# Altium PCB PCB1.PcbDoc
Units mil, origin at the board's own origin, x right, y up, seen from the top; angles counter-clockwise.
Board outline 2353 x 1336 mil, 2 copper layers (Top Layer, Bottom Layer), stack 60.4 mil thick; 21 components, 12 nets, 70 pads, 21 vias.
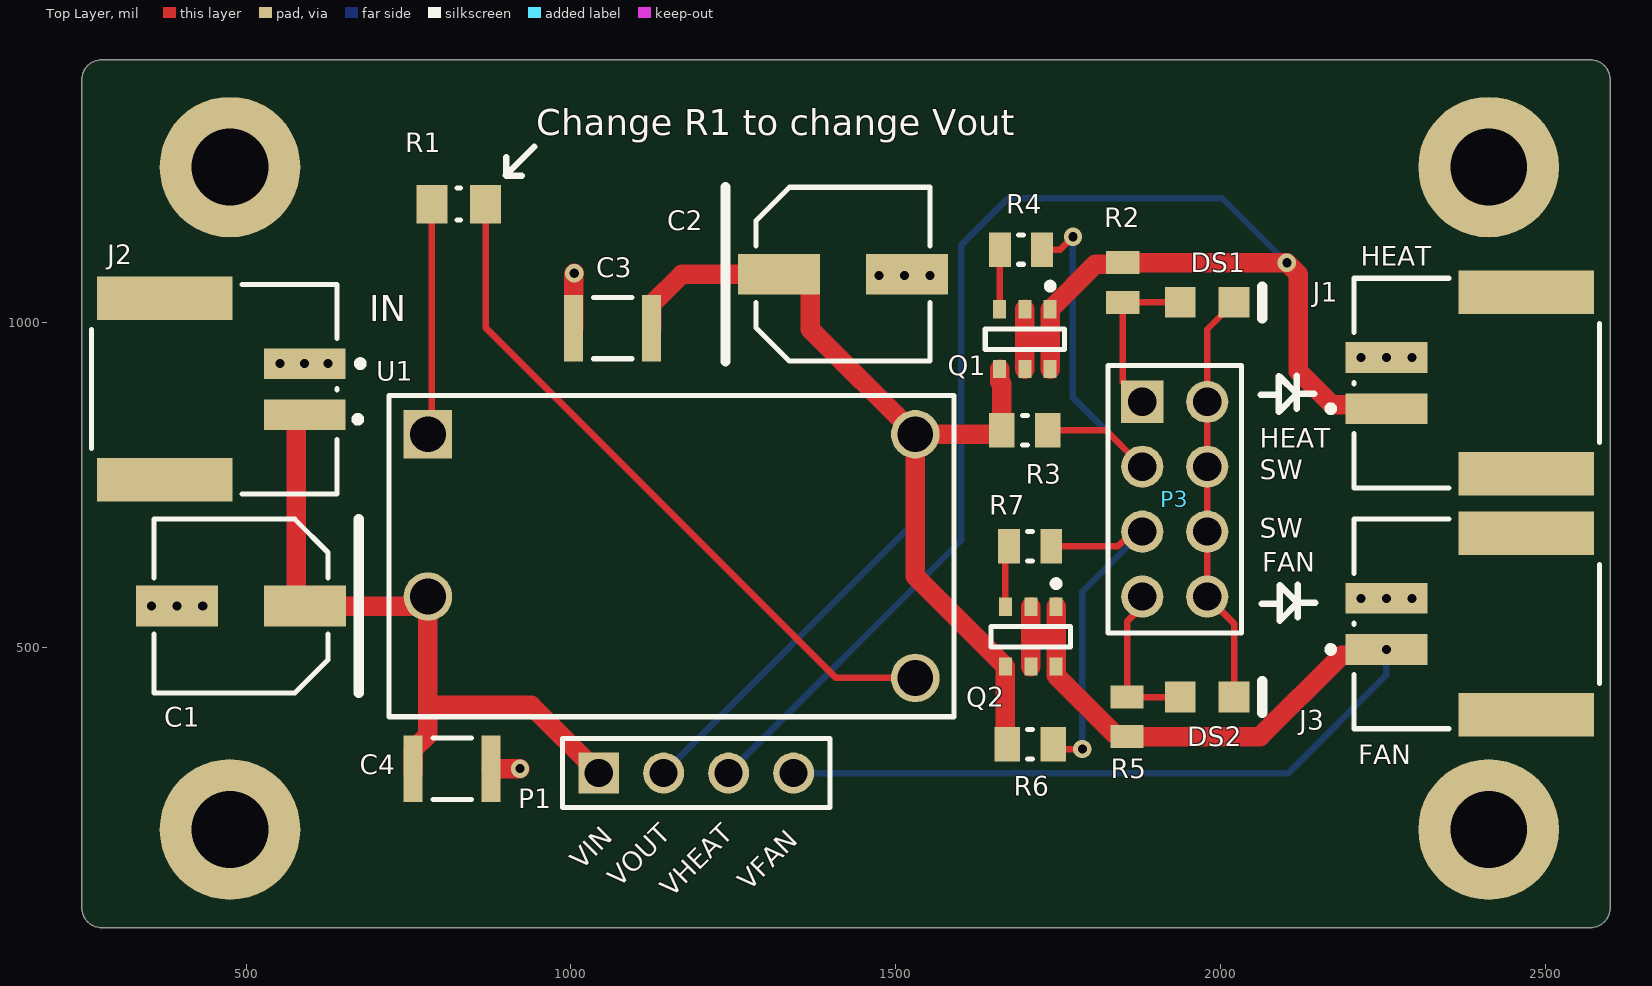
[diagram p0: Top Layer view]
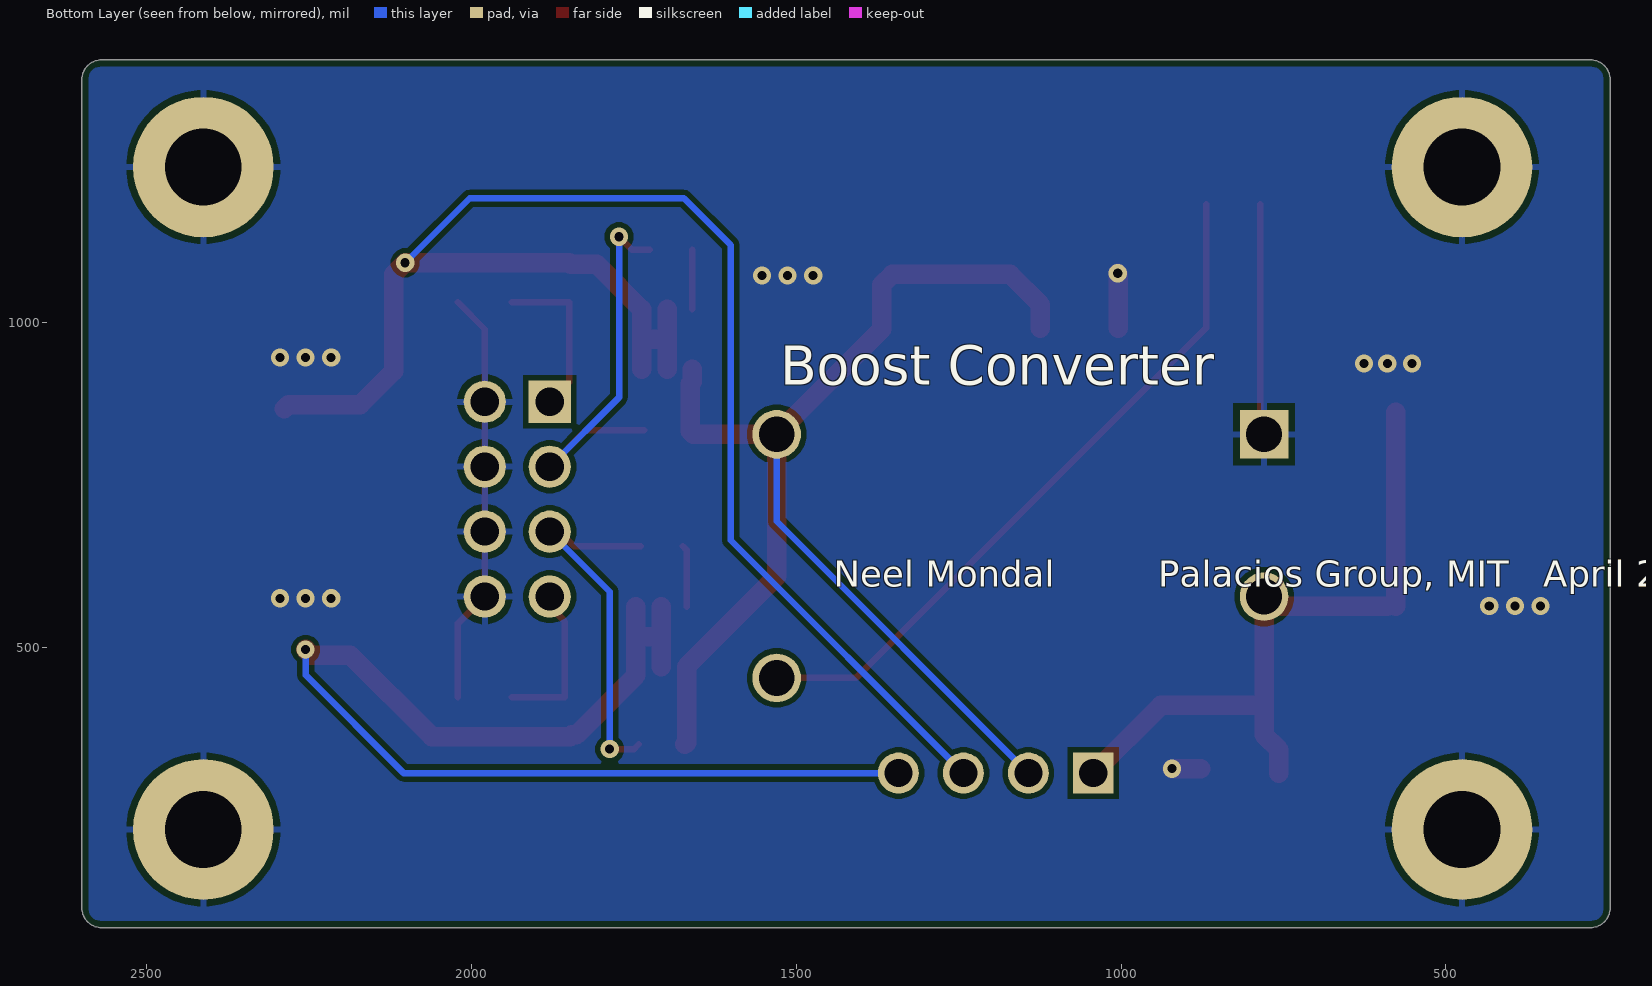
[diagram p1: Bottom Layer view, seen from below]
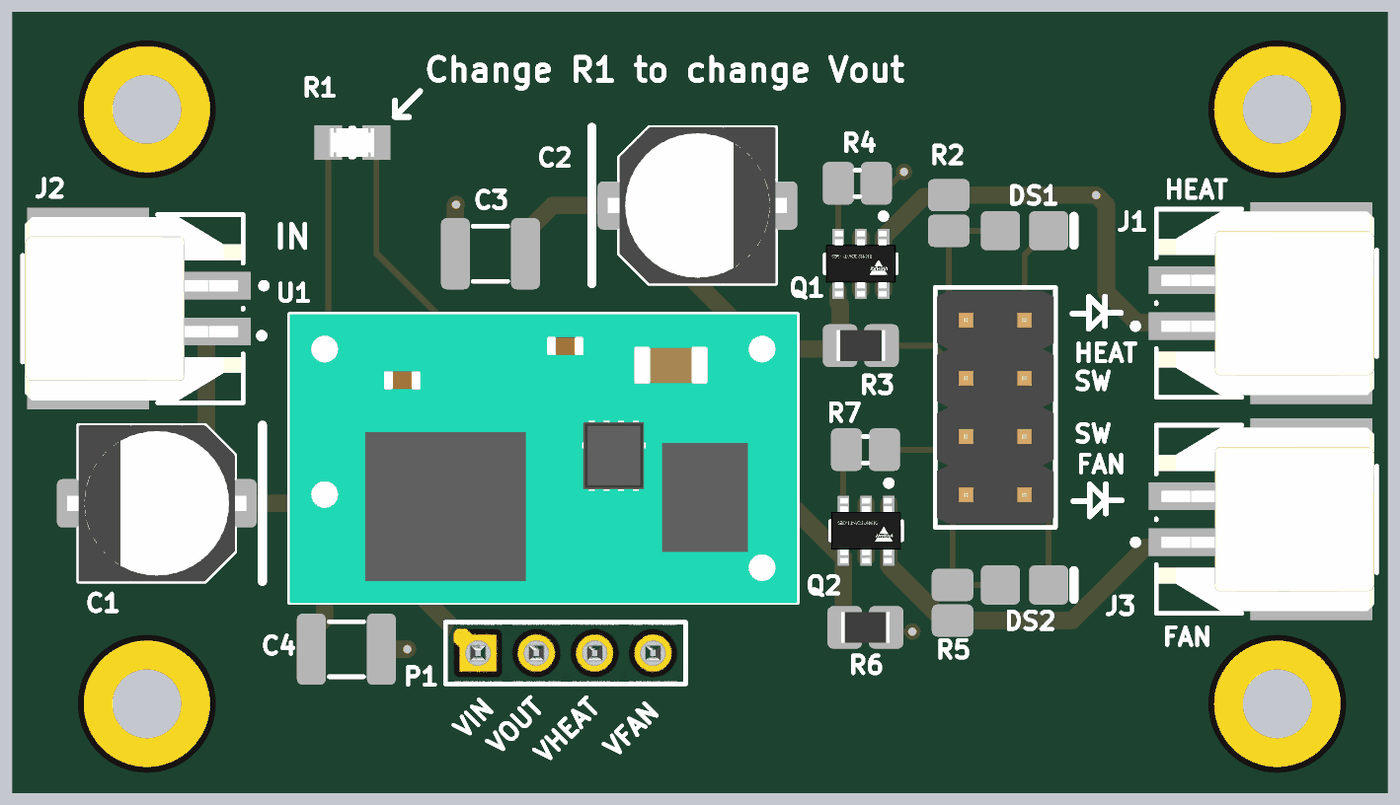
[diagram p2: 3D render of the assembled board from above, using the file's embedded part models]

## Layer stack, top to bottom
Top Solder: solder mask 0.5, Solder Resist, Dk 3.3
Top Layer: signal copper 0.7
Dielectric1: core 59, FR-4, Dk 4.3
Bottom Layer: signal copper 0.7
Bottom Solder: solder mask 0.5, Solder Resist, Dk 3.3

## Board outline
247,99 247,1375 cw(c277,1375) 277,1405 2570,1405 cw(c2570,1375) 2600,1375 2600,99 cw(c2570,99) 2570,69 277,69 cw(c277,99)

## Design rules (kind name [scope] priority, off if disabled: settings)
BoardOutlineClearance [All] p1: gap=10 ignorepadtopadclearanceinfootprint=FALSE
Clearance [All] p1: gap=8 ignorepadtopadclearanceinfootprint=FALSE except(12: Arc-Via Track-Via)
DiffPairsRouting [All] p1: maxlimit=10 minlimit=10 mostfreqgap=10 toplayer_minwidth=10 toplayer_maxwidth=10 toplayer_prefwidth=10 bottomlayer_minwidth=10 bottomlayer_maxwidth=10 bottomlayer_prefwidth=10 maxuncoupledlength=500
HoleSize [All] p1: absolutevalues=TRUE maxlimit=300 minlimit=12 maxpercent=80.000 minpercent=20.000
MinimumAnnularRing [All] p1: minimumring=7
MinimumSolderMaskSliver [All] p1: minsoldermaskwidth=5
PasteMaskExpansion [All] p1: expansion=10
PlaneClearance [All] p1: clearance=15
PlaneConnect [All] p1: pad.planeconnectstyle=Relief pad.reliefexpansion=20 pad.reliefentries=4 pad.reliefconductorwidth=10 pad.reliefairgap=10 via.planeconnectstyle=Direct via.reliefexpansion=20 via.reliefentries=4 via.reliefconductorwidth=10 via.reliefairgap=10
PolygonConnect [All] p1: thpad.connectstyle=Relief thpad.reliefconductorwidth=10 thpad.reliefentries=4 thpad.polygonreliefangle="90 Angle" thpad.airgapwidth=10 smdpad.connectstyle=Relief smdpad.reliefconductorwidth=10 smdpad.reliefentries=4 smdpad.polygonreliefangle="90 Angle" smdpad.airgapwidth=10 via.connectstyle=Direct via.reliefconductorwidth=10 via.reliefentries=4 via.polygonreliefangle="90 Angle" via.airgapwidth=10
RoutingVias [All] p1: holewidth=14 width=28 viastyle="Through Hole" minholewidth=14 minwidth=28 maxholewidth=14 maxwidth=28
SMDNeckDown [All] p1: percent=150.000
SilkToSolderMaskClearance SilkscreenOverComponentPads [IsPad] p1: minsilkscreentomaskgap=4 clearancetoexposedcopper=TRUE
SolderMaskExpansion [All] p1: expansion=10 istentingtop=FALSE
Width [All] p1: maxlimit=30 minlimit=10 preferedwidth=10
23 further rules are at their usual default settings.

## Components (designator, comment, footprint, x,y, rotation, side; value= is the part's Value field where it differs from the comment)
C1 "100uF" PNSC-FK-V-D8_V 492,564 r180 top
C2 "100uF" PNSC-FK-V-D8_V 1419,1075 r0 top
C3 "22uF" MURA-1210_H_2.7_L 1064,992.17 r0 top
C4 "22uF" MURA-1210_H_2.7_L 817.04,313.71 r0 top
DS1 "HSMD-C170" AVAG-HSMX-C170_V 1979.7,1031.69 r0 top
DS2 "HSMD-C170" AVAG-HSMX-C170_V 1979.7,423.94 r0 top
J1 "502352-0200" FP-502352-0200-MFG 2394.5,907.34 r90 top locked
J2 "502352-0200" FP-502352-0200-MFG 451,898 r270 top locked
J3 "502352-0200" FP-502352-0200-MFG 2394.5,536.62 r90 top locked
P1 "61300411121" 61300411121 1192.74,307 r0 top
P3 "61300821121" 61300821121 1929.7,728.63 r270 top
Q1 "SI3493DDV-T1-GE3" FP-C-06593-MFG 1698.93,974.99 r270 top
Q2 "SI3493DDV-T1-GE3" FP-C-06593-MFG 1708.05,516.93 r270 top
R1 "12k" FP-CRCW0805-e3-IPC_A 827.2,1183 r0 top
R2 "1k" RESC2013X55X40LL15T20 1849.78,1062.2 r90 top
R3 "10k" RESC2013X60X35NL10T20 1698.93,834.61 r0 top
R4 "100" RESC2013X50X30LL20T20 1692.98,1112.99 r180 top
R5 "1k" RESC2013X55X40LL15T20 1856.23,393.43 r270 top
R6 "10k" RESC2013X60X35NL10T20 1706.98,351.11 r0 top
R7 "100" RESC2013X50X30LL20T20 1706.98,655.99 r180 top
U1 "PTN04050CAD" EUU0004A 1155,641 r0 top

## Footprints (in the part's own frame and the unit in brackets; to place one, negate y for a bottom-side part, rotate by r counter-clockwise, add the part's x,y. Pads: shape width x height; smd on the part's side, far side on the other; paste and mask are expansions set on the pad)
61300411121 [mm] "Pin Header, pitch 2.54 mm, THT, Vertical, single row, 4p"
  rect 1.6x1.6 hole 1.1: 1(-3.81,0)
  round 1.6 hole 1.1: 2(-1.27,0) 3(1.27,0) 4(3.81,0)
  silkscreen extent -5.23,-1.35 5.23,1.35, body extent -5.08,-1.27 5.08,1.27, height 8.57
61300821121 [mm] "Pin Header, pitch 2.54 mm, THT, Vertical, dual row, 8p"
  rect 1.65x1.65 hole 1.1: 1(-3.81,-1.27)
  round 1.65 hole 1.1: 2(-3.81,1.27) 3(-1.27,-1.27) 4(-1.27,1.27) 5(1.27,-1.27) 6(1.27,1.27) 7(3.81,-1.27) 8(3.81,1.27)
  silkscreen extent -5.23,-2.62 5.23,2.62, body extent -5.08,-2.54 5.08,2.54, height 8.59
AVAG-HSMX-C170_V [mm] "SMD, 2-Leads, Body 2x1.25mm, Height 0.8mm"
  rect 1.2x1.2 smd: 1(-1.05,0) 2(1.05,0)
  silkscreen extent 2.15,-0.63 2.15,0.63, body extent -1,-0.63 1,0.63, height 0.8
EUU0004A [mm] "Module, 4-Leads, Body 22.1x12.57mm"
  rect 1.9x1.9 hole 1.4: 1(-9.53,4.765)
  round 1.9 hole 1.4: 2(-9.53,-1.585) 3(9.53,-4.765) 4(9.53,4.765)
  silkscreen extent -12.4,-6.28 11.05,6.28, body extent -11.05,-6.28 11.04,6.29, height 7.8
FP-502352-0200-MFG [mm]
  rect 1.2x3.2 smd paste+0 mask+0: 1(-1,3.53) 2(1,3.53)
  rect 1.7x5.3 smd paste+0 mask+0: 3(-3.55,-1.95) 4(3.55,-1.95)
  silkscreen extent -4.1,-4.8 4.1,5.83, body extent -4.5,-4.9 4.5,5.23, height 0.25
FP-C-06593-MFG [mil]
  rect 28x20 smd paste+0 mask+0: 1(-46,39) 2(-46,0) 3(-46,-39) 4(46,-39) 5(46,0) 6(46,39)
  silkscreen extent -87,-61 16,61, body extent -64,-65 64,65, height 10
FP-CRCW0805-e3-IPC_A [mil]
  rect 47.5x59.38 smd paste+0 mask+0: 1(-41.37,0) 2(41.37,0)
  silkscreen extent -3,-25 3,25, body extent -85,-49 85,49, height 10
MURA-1210_H_2.7_L [mm] "Chip Capacitor, 2-Leads, Body 3.5x2.7mm, IPC High Density"
  rect 0.75x2.6 smd: 1(-1.525,0) 2(1.525,0)
  silkscreen extent -0.75,-1.2 0.75,1.2, body extent -1.75,-1.35 1.75,1.35, height 2.7
PNSC-FK-V-D8_V [mm] "CAPAE, 2-Leads, Body 6.80x6.80mm"
  rect 3.2x1.6 smd: 1(-2.5,0) 2(2.5,0)
  silkscreen extent -4.6,-3.4 3.4,3.4, body extent -3.9,-3.4 3.9,3.4, height 8
RESC2013X50X30LL20T20 [mm] "Chip Resistor, 2-Leads, Body 2.00x1.25mm, IPC High Density"
  rect 0.85x1.35 smd: 1(-0.825,0) 2(0.825,0)
  silkscreen extent -0.1,-0.58 0.1,0.58, body extent -1.1,-0.73 1.1,0.73, height 0.5
RESC2013X55X40LL15T20 [mm] "Chip Resistor, 2-Leads, Body 2.00x1.25mm, IPC High Density"
  rect 0.9x1.3 smd: 1(-0.775,0) 2(0.775,0)
  body extent -1.07,-0.7 1.07,0.7, height 0.55
RESC2013X60X35NL10T20 [mm] "Chip Resistor, 2-Leads, Body 2.1x1.35mm, IPC Medium Density"
  rect 1x1.35 smd: 1(-0.9,0) 2(0.9,0)
  silkscreen extent -0.1,-0.58 0.1,0.58, body extent -1.05,-0.68 1.05,0.67, height 0.6

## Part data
C1 C2: library part CMP-2000-06206-1, "Aluminum Electrolytic Capacitor, 100 uF, +/- 20%, 25 V, 2-Pin SMD (Size Code D8), -55 to 105 degC, RoHS, Tape and Reel", Capacitance=100µF, Case Size/Dimension=Ø6.3x7.7mm, Lifetime@Temperature=2000Hrs@105°C, Manufacturer=Panasonic, Operating Temp Range=-55to+105°C, Operating Temp-Max=105°C, Package Description="2-Pin Electrolytic Aluminum Capacitor, Body 6.6 x 6.6 mm", Package Reference=FK-V-D8, Rated Voltage=25V, Ripple Current=280mA
C3 C4: library part CMP-2000-06361-1, "Chip Monolithic Ceramic Capacitor, 22 uF, +/- 10%, -55 to 85 degC, 2-Pin SMD (1210), RoHS, Tape and Reel", Capacitance=22µF, Manufacturer=Murata, Operating Temperature=-55°C~85°C, Package / Case=1210(3225Metric), Package Description="2-Pin Surface Mount Device, Body 3.2 x 2.5 mm", Package Reference=1210, Ratings=-, Standard Package=1,000, Temperature Coefficient=X5R, Tolerance=±10%, Voltage - Rated=16V
DS1 DS2: library part CMP-2000-06421-1, "LED Uni-Color Orange, 52 mW, 20 mA, -40 to 85 degC, 2-Pin SMD, RoHS, Tape and Reel", Forward Current If=20mA, Forward Voltage=2.2V, LED Colour=Orange, Manufacturer=Avago, Operating Temperature Max=85°C, Operating Temperature Min=-30°C, Operating Temperature Range=-30°Cto+85°C, Opto Case Style=SMD, Package Description="2-Pin Surface Mount Device, Body 2 x 1.25 mm, Height 0.8 mm", Package Reference=HSMX-C170, Power Dissipation Pd=52mW, Storage Temperature Min=-40°C
J1 J2 J3: library part CMP-04776-000115-1, "CONN HEADER SMD R/A 2POS 2MM", Ambient Temperature Range High=+105°C, Ambient Temperature Range Low=-40°C, Current Rating=3A, Manufacturer=Molex, Temperature="-40°C to +105°C", Voltage Rating=125V
P1: library part CMP-1502-01064-1, "THT Vertical Pin Header WR-PHD, Pitch 2.54 mm, Single Row, 4 pins", Contact Resistance=20mOhm, Manufacturer="Wurth Elektronik", Operating Temperature=-40to105degC, Rated Current=3A, Withstanding Voltage=500VAC, Working Voltage=250VAC
P3: library part CMP-1502-01078-1, "THT Vertical Pin Header WR-PHD, Pitch 2.54 mm, Dual Row, 8 pins", Contact Resistance=20mOhm, Manufacturer="Wurth Elektronik", Operating Temperature=-40to105degC, Rated Current=3A, Withstanding Voltage=500VAC, Working Voltage=250VAC
Q1 Q2: library part CMP-02550-000156-1, "MOSFET P-CHANNEL 20V 8A 6TSOP", Continuous Drain Current=-7.5A, Drain To Source Breakdown Voltage=-20V, Drain To Source Resistance=0.02Ω, Gate To Source Voltage=8V, Input Capacitace At Vds="1825pF @ -10V", Manufacturer=Vishay, Max Forward Diode Voltage=-1.2V, Max Junction Temp=+150°C, Package=C-06593, Power Dissipation=2W, Pulse Drain Current=-32A, Temperature="-55°C to +150°C", Temperature Range Low=-55°C, Typ Forward Diode Voltage=-0.8V
R1: library part CMP-2001-04934-2, "RES Thick Film, 12kΩ, 1%, 0.125W, 100ppm/°C, 0805", Case Code (Imperial)=0805, Case Code (Metric)=2012, Max Operating Temperature=155°C, Max Power Dissipation=125mW, Min Operating Temperature=-55°C, Package Quantity=10, Resistance=12kR, Temperature Coefficient=100ppm/°C, Tolerance=1%, Voltage Rating=150V
R2 R5: library part CMP-2001-04738-1, "TNPW08051K00BEEN", Manufacturer="Vishay Dale"
R3 R6: library part CMP-1659-00013-4, "Chip Resistor, 10 KOhm, +/- 1%, 0.125 W, -55 to 155 degC, 0805 (2012 Metric), RoHS, Tape and Reel", Manufacturer=Yageo, Max Operating Temperature="155 degC", Min Operating Temperature="-55 degC", Package Quantity=5000, Voltage Rating="150 V"
R4 R7: library part CMP-2001-04901-1, Manufacturer="Vishay Dale", Part Number=CRCW0805100RFKEA
U1: library part CMP-0387-00658-2, "12 W, 3.3 / 5 V Input, Wide Adjust Output Boost Converter, -40 to 85 degC, 4-pin Module (EUU4), Pb-Free (RoHS)", Manufacturer="Texas Instruments"

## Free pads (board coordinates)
  round 216.54 hole 118.11: 5(475,220) 5(475,1240) 5(2413,220) 5(2413,1240)

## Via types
v1: diameter 28, hole 14, Top Layer to Bottom Layer, tented both sides, 21 vias

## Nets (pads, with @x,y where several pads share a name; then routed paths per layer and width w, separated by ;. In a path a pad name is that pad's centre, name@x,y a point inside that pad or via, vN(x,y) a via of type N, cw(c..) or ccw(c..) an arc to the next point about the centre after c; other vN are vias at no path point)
FAN_LED_HI: DS2.1 P3.7 R5.1 | length 246.5
  Top Layer w10: P3.7 1879.7,563.76 1856.23,540.29 R5.1 DS2.1
FAN_SW: P3.5 R6.2 R7.1 | length 570.7
  Top Layer w10: R7.1 1842.19,655.99 1864.83,678.63 P3.5 ; R6.2 1749.72,343.8 v1(1787.37,343.8)
  Bottom Layer w10: v1(1787.37,343.8) 1787.37,586.3 P3.5
GND: C1.2 C2.2 C3.1 C4.2 DS1.2 DS2.2 J1.2 J2.1 J3.2 P3.2 P3.4 P3.6 P3.8 pad.5 R1.1 U1.1 | length 1128.1
  Top Layer w10: U1.1 785.83,834.63 R1.1 ; DS2.2 2021.04,537.29 P3.8 P3.6 P3.4 P3.2 1979.7,990.35 DS1.2
  Top Layer w30: C4.2 v1(921.53,313.71) ; C3.1 1003.96,1075.33 v1(1005.11,1076.48)
  other v1: 354.15,564 393.57,564 433,564 2216.16,575.99 2255.53,575.99 2294.96,575.99 552.05,937.37 589.98,937.37 625.86,937.37 2216.16,946.71 2255.53,946.71 2294.96,946.71 1474,1073 1513.43,1073 1552.86,1073
HEAT_LED_HI: DS1.1 P3.1 R2.1 | length 254
  Top Layer w10: P3.1 1849.78,908.55 R2.1 DS1.1
HEAT_SW: P3.3 R3.2 R4.1 | length 622.5
  Top Layer w10: R4.1 1753.32,1112.99 v1(1773.01,1132.67) ; R3.2 1823.72,834.61 P3.3
  Bottom Layer w10: v1(1773.01,1132.67) 1773.01,885.32 P3.3
NetQ1_3: Q1.3 R4.2 | length 92.2
  Top Layer w10: Q1.3 1659.93,1112.42 R4.2
NetQ2_3: Q2.3 R7.2 | length 95.3
  Top Layer w10: Q2.3 1669.05,650.53 R7.2
NetR1_2: R1.2 U1.3 | length 1075.2
  Top Layer w10: R1.2 868.58,992.9 1408.08,453.4 U1.3
VFAN: J3.1 P1.4 Q2.1 Q2.2 Q2.5 Q2.6 R5.2 | length 1854.5
  Top Layer w30: Q2.5 1708.05,516.93 ; Q2.2 1708.05,516.93 ; Q2.1 1747.05,516.93 ; v1(2255.53,497.25) 2246.91,488.62 2186.92,488.62 2061.21,362.92 1848.36,362.92 1845.64,365.64 1838.71,365.64 1747.05,457.3 1747.05,516.93 ; 1708.05,516.93 1747.05,516.93
  Bottom Layer w10: P1.4 2104.65,307 2255.53,457.88 v1(2255.53,497.25)
VHEAT: J1.1 P1.3 Q1.1 Q1.2 Q1.5 Q1.6 R2.2 | length 2517
  Top Layer w30: Q1.5 1698.93,974.99 ; Q1.2 1698.93,974.99 ; Q1.6 1737.93,974.99 ; J1.1@2288.11,867.97 2281.91,874.16 2171.47,874.16 2120,925.63 2120,1075 v1(2102.28,1092.72) R2.2 1847.06,1090 1806.95,1090 Q1.1 1737.93,974.99 ; 1698.93,974.99 1737.93,974.99
  Bottom Layer w10: P1.3 1601,665.26 1601,1119.91 1673.09,1191.99 2003.01,1191.99 v1(2102.28,1092.72)
VIN: C1.1 C4.1 J2.2 P1.1 U1.2 | length 1081.1
  Top Layer w30: C1.1@576.98,564 J2.2@576.98,862.63 ; C1.1 753.08,564 767.68,578.6 U1.2 779.8,410.99 ; C4.1@757,307 C4.1 757,342.94 779.8,365.75 779.8,410.99 ; P1.1 938.75,410.99 779.8,410.99
VOUT: C2.1 C3.2 P1.2 Q1.4 Q2.4 R3.1 R6.1 U1.4 | length 2054.1
  Top Layer w30: C3.2 1124.04,1028.11 1170.93,1075 C2.1 1352.07,1075 1368.57,1058.5 1368.57,990.23 U1.4 ; Q1.4 1659.93,909.75 1663.5,906.18 R3.1 1663.5,833.28 1658.82,828.6 U1.4 ; R6.1 1669.05,353.61 Q2.4 1530.2,609.78 U1.4
  Bottom Layer w10: P1.2 1530.2,694.46 U1.4
pads on no net: J1.3 J1.4 J2.3 J2.4 J3.3 J3.4

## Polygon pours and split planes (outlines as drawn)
GND on Bottom Layer "GND_L02_P000" (solid, pour order 0): 247,1439.03 247,1221 247,32 2614,32 2614,1452.94

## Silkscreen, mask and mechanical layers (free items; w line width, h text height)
Top Overlay:
  lines w10: 899.72,1227.49 943.35,1271.12 ; 900.38,1254.89 900.38,1226.83 924.44,1226.83 ; 2062.09,889.42 2088.68,889.42 ; 2063.49,567.66 2090.08,567.66 ; 2117.69,868.25 2117.69,918.43 ; 2119.08,546.49 2119.08,596.66 ; 2144.75,890.81 2117.47,890.81 ; 2146.14,569.05 2118.86,569.05 ; 2117.47,890.81 2090.08,918.2 2090.08,863.42 2117.47,890.81 ; 2118.86,569.05 2091.47,541.65 2091.47,596.44 2118.86,569.05
  text "Change R1 to change Vout" at 946.75,1289.02 h40
  text "HEAT" at 2215.74,1088.06 h30
  text "IN" at 689.24,1002.45 h40
  text "HEAT" at 2060.62,807.72 h30
  text "SW" at 2060.62,759.54 h30
  text "SW" at 2060.62,669.42 h30
  text "FAN" at 2064.8,616.67 h30
  text "FAN" at 2212.53,320.71 h30
  text "VIN" at 1017,156.9 h30 r45
  text "VOUT" at 1074,129.9 h30 r45
  text "VFAN" at 1274.34,124.44 h30 r45
  text "VHEAT" at 1155,114.54 h30 r45
Bottom Overlay:
  text "Boost Converter" at 1525,905 h60
  text "Neel Mondal         Palacios Group, MIT   April 2023" at 1442,594 h40
Board:
  the board outline again, w5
